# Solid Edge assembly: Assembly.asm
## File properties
Author: Deepak Maini
Template: Normal.asm
Last saved by: MYPC
Revision: 10
Application: Solid Edge
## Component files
Casting.par
Brasses.par
Cap.par
Bolt.par
Nut.par
Lock Nut.par
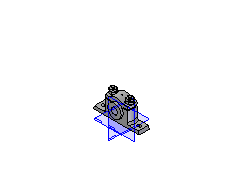
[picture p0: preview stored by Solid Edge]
